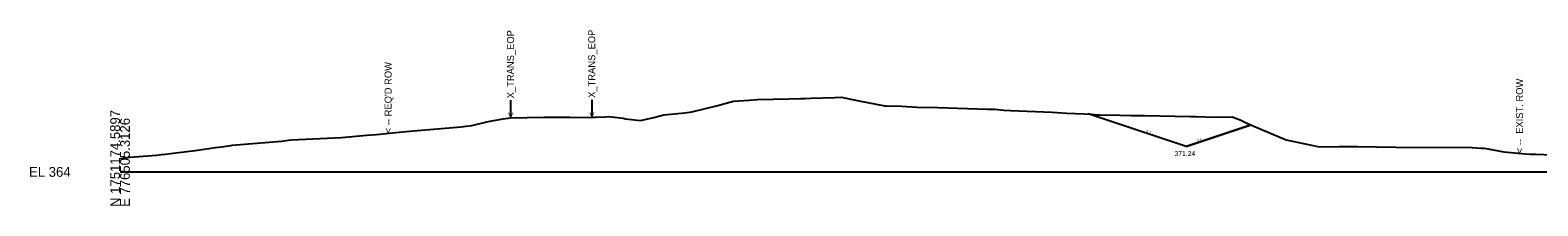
# Model space of a CAD drawing. Extents: x 776426 to 854588, y 1736205 to 1756790.
# Drawn here: x 805845.1 to 806276, y 1738205.1 to 1738255.2 of the extents above; entities that cross this region are included whole.
import ezdxf

# ---------------------------------------------------------------- set-up
doc = ezdxf.new("R2010")
doc.units = 0
for name, color, linetype in [('DTM CONTOURS_MAJOR_TX', 7, 'Continuous'), ('DTM_X_FLOW_ARROWS', 7, 'Continuous'), ('X_TRANS_EOP', 7, 'Continuous'), ('XS_M_SHAPES_EARTHWORK', 7, 'Continuous'), ('XS_P_FINISHED_GRADE', 7, 'Continuous'), ('XS_P_ROW', 7, 'Continuous'), ('XS_P_TX_DCH', 7, 'Continuous'), ('XS_P_TX_FS_BS', 7, 'Continuous'), ('XS_X_PAVEMENT', 7, 'Continuous'), ('XS_X_ROW', 7, 'Continuous')]:
    doc.layers.add(name, color=color, linetype=linetype)

msp = doc.modelspace()

# ---------------------------------------------------------------- linework, layer by layer
at = {"layer": 'DTM CONTOURS_MAJOR_TX'}
msp.add_line((805870.79, 1738214.76), (806370.79, 1738214.76), dxfattribs=at)
at = {"layer": 'DTM_X_FLOW_ARROWS'}
msp.add_lwpolyline([(805870.79, 1738218.6), (805873.58, 1738218.94), (805881.19, 1738219.58), (805882.61, 1738219.7), (805883.78, 1738219.82), (805886.74, 1738220.17), (805892.24, 1738220.85), (805898.1, 1738221.72), (805899.77, 1738221.92), (805902.48, 1738222.34), (805902.85, 1738222.36), (805916.98, 1738223.56), (805918.91, 1738223.81), (805919.76, 1738223.89), (805934.07, 1738224.63), (805941.28, 1738225.22), (805944.05, 1738225.47), (805950.53, 1738226.12), (805951.49, 1738226.21), (805954.68, 1738226.45), (805968.26, 1738227.67), (805968.91, 1738227.72), (805971.36, 1738227.98), (805976, 1738229.18), (805980.3, 1738229.88), (805982.39, 1738230.21), (805991.93, 1738230.38), (805993.97, 1738230.41), (805995.13, 1738230.41), (805999.32, 1738230.38), (806005.6, 1738230.34), (806006.39, 1738230.35), (806006.81, 1738230.36), (806009.58, 1738230.5), (806010.45, 1738230.54), (806011.28, 1738230.49), (806014.59, 1738230.08), (806015.24, 1738229.95), (806019.56, 1738229.45), (806023.37, 1738230.34), (806026.2, 1738231.03), (806032.17, 1738231.61), (806034.23, 1738231.92), (806041.25, 1738233.67), (806046.11, 1738234.96), (806050.59, 1738235.29), (806053.02, 1738235.42), (806061.92, 1738235.66), (806065.27, 1738235.73), (806066.56, 1738235.74), (806068.21, 1738235.79), (806075.08, 1738236.02), (806076.97, 1738236.08), (806081.98, 1738235.09), (806089.4, 1738233.63), (806089.74, 1738233.63), (806094.23, 1738233.52), (806098.57, 1738233.25), (806104.55, 1738233.2), (806118.73, 1738232.66), (806120.84, 1738232.71), (806123.39, 1738232.38), (806125.29, 1738232.29), (806137.24, 1738231.86), (806141.39, 1738231.56), (806146.32, 1738231.38), (806148.47, 1738231.27), (806150.12, 1738231.06), (806150.7, 1738231.05), (806156.57, 1738230.95), (806159.78, 1738230.91), (806163.63, 1738230.85), (806176.72, 1738230.63), (806177.27, 1738230.63), (806178.27, 1738230.59), (806183.54, 1738230.4), (806188.68, 1738230.51), (806190.91, 1738229.6), (806193.06, 1738228.61), (806204.05, 1738223.94), (806213.15, 1738222.01), (806216.75, 1738221.96), (806219.21, 1738221.97), (806224.35, 1738222.04), (806235.42, 1738221.86), (806257.27, 1738221.72), (806259.69, 1738221.57), (806260.71, 1738221.52), (806261.68, 1738221.33), (806266.32, 1738220.46), (806272.38, 1738219.92), (806273.73, 1738219.85), (806275.44, 1738219.78), (806282.37, 1738219.57)], dxfattribs=at)
at = {"layer": 'X_TRANS_EOP'}
for p, q in [((805982.39, 1738235.21), (805982.39, 1738230.21)), ((805982.39, 1738235.21), (805982.39, 1738230.21)), ((806005.6, 1738235.34), (806005.6, 1738230.34)), ((806005.6, 1738235.34), (806005.6, 1738230.34))]:
    msp.add_line(p, q, dxfattribs=at)
at = {"layer": 'XS_M_SHAPES_EARTHWORK'}
msp.add_lwpolyline([(806156.57, 1738230.95), (806159.78, 1738230.91), (806163.63, 1738230.85), (806176.72, 1738230.63), (806177.27, 1738230.63), (806178.27, 1738230.59), (806183.54, 1738230.4), (806188.68, 1738230.51), (806190.91, 1738229.6), (806193.06, 1738228.61), (806194.03, 1738228.19), (806175.45, 1738222), (806147.51, 1738231.32), (806148.47, 1738231.27), (806150.12, 1738231.06), (806150.7, 1738231.05)], close=True, dxfattribs=at)
at = {"layer": 'XS_P_FINISHED_GRADE'}
for q in [(806147.51, 1738231.32), (806194.03, 1738228.19)]:
    msp.add_line((806175.45, 1738222), q, dxfattribs=at)

# ---------------------------------------------------------------- texts
at = {"layer": 'DTM CONTOURS_MAJOR_TX'}
for s, p in [('N 1751174.5897', (805870.79, 1738204.76)), ('E 776505.3126', (805873.59, 1738204.76))]:
    msp.add_text(s, height=2.8, rotation=90, dxfattribs=at).set_placement(p)
msp.add_text('EL 364', height=2.8, dxfattribs=at).set_placement((805844.79, 1738213.36))
at = {"layer": 'XS_P_ROW'}
msp.add_text("< -- REQ'D ROW", height=2, rotation=90, dxfattribs=at).set_placement((805948.4, 1738225.8))
at = {"layer": 'XS_P_TX_DCH'}
msp.add_text('371.24', height=1.4, dxfattribs=at).set_placement((806172.17, 1738219.3))
at = {"layer": 'XS_P_TX_FS_BS'}
for rotation, p in [(341.5651, (806163.87, 1738226.06)), (18.4349, (806178.65, 1738223.22))]:
    msp.add_text('3:1', height=0.8, rotation=rotation, dxfattribs=at).set_placement(p)
at = {"layer": 'XS_X_PAVEMENT'}
for p in [(805983.39, 1738230.21), (806006.6, 1738230.34)]:
    msp.add_text('< --  X_TRANS_EOP', height=2, rotation=90, dxfattribs=at).set_placement(p)
at = {"layer": 'XS_X_ROW'}
msp.add_text('< --  EXIST. ROW', height=2, rotation=90, dxfattribs=at).set_placement((806271.76, 1738220.07))

doc.saveas('drawing.dxf')
